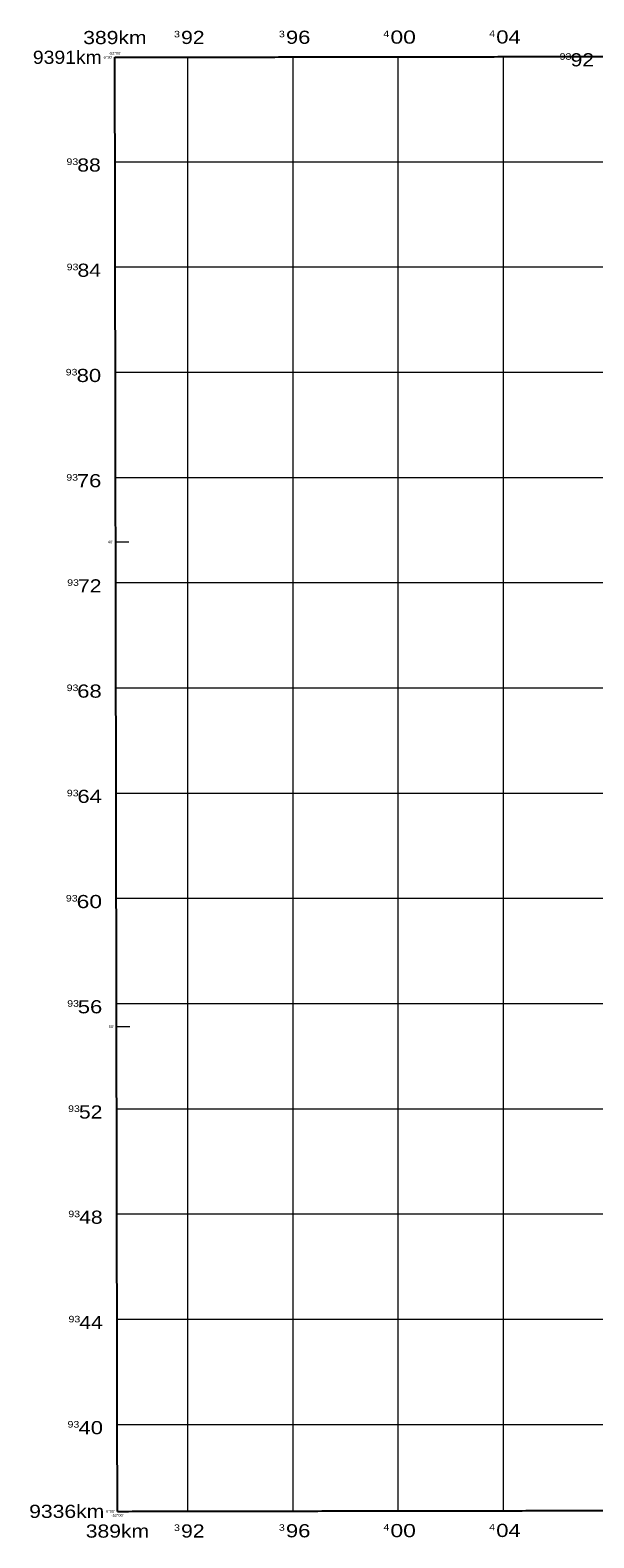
# Model space of a CAD drawing. Extents: x 386 to 448, y 9335.7 to 9393.1.
# Drawn here: x 386 to 407.4, y 9335.7 to 9393 of the extents above; entities that cross this region are included whole.
import ezdxf
from ezdxf.enums import TextEntityAlignment as Align

# ---------------------------------------------------------------- set-up
doc = ezdxf.new("R2010")
doc.units = 0
doc.header["$LTSCALE"] = 0.1
for name, color, linetype, lineweight in [('1', 7, 'Continuous', 25), ('2', 7, 'Continuous', 13), ('4', 7, 'Continuous', 13)]:
    doc.layers.add(name, color=color, linetype=linetype, lineweight=lineweight)
doc.layers.add('5', color=7, linetype='Continuous')
doc.layers.add('6', color=7, linetype='Continuous')

msp = doc.modelspace()

# ---------------------------------------------------------------- linework, layer by layer
at = {"layer": '1'}
for points in [[(389.2279, 9391.9712), (390.3584, 9391.9731), (391.4888, 9391.975), (392.6192, 9391.9768), (393.7496, 9391.9786), (394.8801, 9391.9804), (396.0105, 9391.9822), (397.1409, 9391.984), (398.2713, 9391.9857), (399.4017, 9391.9875), (400.5321, 9391.9892), (401.6626, 9391.9909), (402.793, 9391.9925), (403.9234, 9391.9942), (405.0538, 9391.9958), (406.1841, 9391.9974), (407.3145, 9391.999), (408.4449, 9392.0006), (409.5753, 9392.0021), (410.7057, 9392.0037), (411.8361, 9392.0052), (412.9664, 9392.0067), (414.0968, 9392.0082), (415.2272, 9392.0096), (416.3576, 9392.0111), (417.4879, 9392.0125), (418.6183, 9392.0139), (419.7487, 9392.0153), (420.879, 9392.0166), (422.0094, 9392.018), (423.1397, 9392.0193), (424.2701, 9392.0206), (425.4004, 9392.0219), (426.5308, 9392.0231), (427.6611, 9392.0244), (428.7915, 9392.0256), (429.9218, 9392.0268), (431.0521, 9392.028), (432.1825, 9392.0292), (433.3128, 9392.0303), (434.4431, 9392.0314), (435.5735, 9392.0325), (436.7038, 9392.0336), (437.8341, 9392.0347), (438.9644, 9392.0358), (440.0947, 9392.0368), (441.2251, 9392.0378), (442.3554, 9392.0388), (443.4857, 9392.0398), (444.616, 9392.0407)], [(389.3246, 9336.6921), (389.3225, 9337.8203), (389.3205, 9338.9484), (389.3184, 9340.0766), (389.3164, 9341.2047), (389.3143, 9342.3329), (389.3123, 9343.4611), (389.3103, 9344.5892), (389.3082, 9345.7174), (389.3062, 9346.8455), (389.3042, 9347.9737), (389.3022, 9349.1018), (389.3001, 9350.23), (389.2981, 9351.3581), (389.2961, 9352.4863), (389.2941, 9353.6144), (389.2921, 9354.7426), (389.2901, 9355.8707), (389.2881, 9356.9988), (389.2861, 9358.127), (389.2841, 9359.2551), (389.2821, 9360.3833), (389.2801, 9361.5114), (389.2782, 9362.6396), (389.2762, 9363.7677), (389.2742, 9364.8959), (389.2722, 9366.024), (389.2703, 9367.1522), (389.2683, 9368.2803), (389.2664, 9369.4084), (389.2644, 9370.5366), (389.2624, 9371.6647), (389.2605, 9372.7929), (389.2586, 9373.921), (389.2566, 9375.0492), (389.2547, 9376.1773), (389.2527, 9377.3054), (389.2508, 9378.4336), (389.2489, 9379.5617), (389.247, 9380.6899), (389.245, 9381.818), (389.2431, 9382.9461), (389.2412, 9384.0743), (389.2393, 9385.2024), (389.2374, 9386.3305), (389.2355, 9387.4587), (389.2336, 9388.5868), (389.2317, 9389.715), (389.2298, 9390.8431), (389.2279, 9391.9712)], [(389.3246, 9336.6921), (390.454, 9336.6942), (391.5835, 9336.6962), (392.7129, 9336.6982), (393.8424, 9336.7002), (394.9718, 9336.7022), (396.1012, 9336.7041), (397.2307, 9336.706), (398.3601, 9336.7079), (399.4895, 9336.7098), (400.619, 9336.7117), (401.7484, 9336.7135), (402.8778, 9336.7153), (404.0072, 9336.7171), (405.1366, 9336.7189), (406.266, 9336.7207), (407.3954, 9336.7224), (408.5248, 9336.7241), (409.6542, 9336.7258), (410.7836, 9336.7275), (411.913, 9336.7291), (413.0424, 9336.7308), (414.1718, 9336.7324), (415.3012, 9336.734), (416.4306, 9336.7355), (417.5599, 9336.7371), (418.6893, 9336.7386), (419.8187, 9336.7401), (420.9481, 9336.7416), (422.0774, 9336.7431), (423.2068, 9336.7445), (424.3362, 9336.7459), (425.4655, 9336.7473), (426.5949, 9336.7487), (427.7242, 9336.75), (428.8536, 9336.7514), (429.9829, 9336.7527), (431.1123, 9336.754), (432.2416, 9336.7553), (433.371, 9336.7565), (434.5003, 9336.7577), (435.6297, 9336.7589), (436.759, 9336.7601), (437.8884, 9336.7613), (439.0177, 9336.7624), (440.147, 9336.7636), (441.2764, 9336.7647), (442.4057, 9336.7658), (443.535, 9336.7668), (444.6643, 9336.7679)]]:
    msp.add_spline(points, degree=3, dxfattribs=at)
at = {"layer": '2'}
for points in [[(391.9999, 9336.697), (391.9999, 9340), (391.9999, 9344), (391.9999, 9348), (391.9999, 9352), (391.9999, 9356), (391.9999, 9360), (391.9999, 9364), (391.9999, 9368), (391.9999, 9372), (391.9999, 9376), (391.9999, 9380), (391.9999, 9384), (391.9999, 9388), (391.9999, 9391.9758)], [(395.9999, 9336.7039), (395.9999, 9340), (395.9999, 9344), (395.9999, 9348), (395.9999, 9352), (395.9999, 9356), (395.9999, 9360), (395.9999, 9364), (395.9999, 9368), (395.9999, 9372), (395.9999, 9376), (395.9999, 9380), (395.9999, 9384), (395.9999, 9388), (395.9999, 9391.9822)], [(399.9999, 9336.7107), (399.9999, 9340), (399.9999, 9344), (399.9999, 9348), (399.9999, 9352), (399.9999, 9356), (399.9999, 9360), (399.9999, 9364), (399.9999, 9368), (399.9999, 9372), (399.9999, 9376), (399.9999, 9380), (399.9999, 9384), (399.9999, 9388), (399.9999, 9391.9884)], [(403.9999, 9336.7171), (403.9999, 9340), (403.9999, 9344), (403.9999, 9348), (403.9999, 9352), (403.9999, 9356), (403.9999, 9360), (403.9999, 9364), (403.9999, 9368), (403.9999, 9372), (403.9999, 9376), (403.9999, 9380), (403.9999, 9384), (403.9999, 9388), (403.9999, 9391.9943)], [(389.2346, 9388), (391.9999, 9388), (395.9999, 9388), (399.9999, 9388), (403.9999, 9388), (407.9999, 9388), (411.9999, 9388), (415.9999, 9388), (419.9999, 9388), (423.9999, 9388), (427.9999, 9388), (431.9999, 9388), (435.9999, 9388), (439.9999, 9388), (444, 9388), (444.6194, 9388)], [(389.2413, 9384), (391.9999, 9384), (395.9999, 9384), (399.9999, 9384), (403.9999, 9384), (407.9999, 9384), (411.9999, 9384), (415.9999, 9384), (419.9999, 9384), (423.9999, 9384), (427.9999, 9384), (431.9999, 9384), (435.9999, 9384), (439.9999, 9384), (443.9999, 9384), (444.6228, 9384)], [(389.2481, 9380), (391.9999, 9380), (395.9999, 9380), (399.9999, 9380), (403.9999, 9380), (407.9999, 9380), (411.9999, 9380), (415.9999, 9380), (419.9999, 9380), (423.9999, 9380), (427.9999, 9380), (431.9999, 9380), (435.9999, 9380), (439.9999, 9380), (443.9999, 9380), (444.6262, 9380)], [(389.255, 9376), (391.9999, 9376), (395.9999, 9376), (399.9999, 9376), (403.9999, 9376), (407.9999, 9376), (411.9999, 9376), (415.9999, 9376), (419.9999, 9376), (423.9999, 9376), (427.9999, 9376), (431.9999, 9376), (435.9999, 9376), (439.9999, 9376), (443.9999, 9376), (444.6296, 9376)], [(389.2619, 9372), (391.9999, 9372), (395.9999, 9372), (399.9999, 9372), (403.9999, 9372), (407.9999, 9372), (411.9999, 9372), (415.9999, 9372), (419.9999, 9372), (423.9999, 9372), (427.9999, 9372), (431.9999, 9372), (435.9999, 9372), (439.9999, 9372), (443.9999, 9372), (444.6331, 9372)], [(389.2688, 9368), (391.9999, 9368), (395.9999, 9368), (399.9999, 9368), (403.9999, 9368), (407.9999, 9368), (411.9999, 9368), (415.9999, 9368), (419.9999, 9368), (423.9999, 9368), (427.9999, 9368), (431.9999, 9368), (435.9999, 9368), (439.9999, 9368), (443.9999, 9368), (444.6365, 9368)], [(389.2758, 9364), (391.9999, 9364), (395.9999, 9364), (399.9999, 9364), (403.9999, 9364), (407.9999, 9364), (411.9999, 9364), (415.9999, 9364), (419.9999, 9364), (423.9999, 9364), (427.9999, 9364), (431.9999, 9364), (435.9999, 9364), (439.9999, 9364), (443.9999, 9364), (444.64, 9364)], [(389.2828, 9360), (391.9999, 9360), (395.9999, 9360), (399.9999, 9360), (403.9999, 9360), (407.9999, 9360), (411.9999, 9360), (415.9999, 9360), (419.9999, 9360), (423.9999, 9360), (427.9999, 9360), (431.9999, 9360), (435.9999, 9360), (439.9999, 9360), (444, 9360), (444.6435, 9360)], [(389.2899, 9356), (391.9999, 9356), (395.9999, 9356), (399.9999, 9356), (403.9999, 9356), (407.9999, 9356), (411.9999, 9356), (415.9999, 9356), (419.9999, 9356), (423.9999, 9356), (427.9999, 9356), (431.9999, 9356), (435.9999, 9356), (439.9999, 9356), (443.9999, 9356), (444.6471, 9356)], [(389.297, 9352), (391.9999, 9352), (395.9999, 9352), (399.9999, 9352), (403.9999, 9352), (407.9999, 9352), (411.9999, 9352), (415.9999, 9352), (419.9999, 9352), (423.9999, 9352), (427.9999, 9352), (431.9999, 9352), (435.9999, 9352), (439.9999, 9352), (444, 9352), (444.6506, 9352)], [(389.3041, 9348), (391.9999, 9348), (395.9999, 9348), (399.9999, 9348), (403.9999, 9348), (407.9999, 9348), (411.9999, 9348), (415.9999, 9348), (419.9999, 9348), (423.9999, 9348), (427.9999, 9348), (431.9999, 9348), (435.9999, 9348), (439.9999, 9348), (443.9999, 9348), (444.6542, 9348)], [(389.3113, 9344), (391.9999, 9344), (395.9999, 9344), (399.9999, 9344), (403.9999, 9344), (407.9999, 9344), (411.9999, 9344), (415.9999, 9344), (419.9999, 9344), (423.9999, 9344), (427.9999, 9344), (431.9999, 9344), (435.9999, 9344), (439.9999, 9344), (443.9999, 9344), (444.6578, 9344)], [(389.3186, 9340), (391.9999, 9340), (395.9999, 9340), (399.9999, 9340), (403.9999, 9340), (407.9999, 9340), (411.9999, 9340), (415.9999, 9340), (419.9999, 9340), (423.9999, 9340), (427.9999, 9340), (431.9999, 9340), (435.9999, 9340), (439.9999, 9340), (443.9999, 9340), (444.6614, 9340)]]:
    msp.add_spline(points, degree=3, dxfattribs=at)
at = {"layer": '4'}
for p, q in [((389.2592, 9373.545), (389.7592, 9373.5458)), ((389.2914, 9355.1186), (389.7914, 9355.1194))]:
    msp.add_line(p, q, dxfattribs=at)

# ---------------------------------------------------------------- texts
at = {"layer": '5'}
for s, rotation, width, p in [("-5°30'", 0.088, 1.05, (389.1282, 9391.9211)), ("40'", 0.091, 1.15, (389.1595, 9373.4949)), ("50'", 0.093, 1.15, (389.1917, 9355.0685)), ("-6°00'", 0.096, 1.1, (389.2248, 9336.642))]:
    msp.add_text(s, height=0.1, rotation=rotation, dxfattribs=dict(at, width=width)).set_placement(p, align=Align.RIGHT)
at = {"layer": '5', "width": 1.1}
for rotation, p in [(0.097, (389.2279, 9392.0713)), (0.103, (389.3251, 9336.4922))]:
    msp.add_text("-52°00'", height=0.1, rotation=rotation, dxfattribs=at).set_placement(p, align=Align.CENTER)
at = {"layer": '6', "width": 1.2}
for p in [(389.228, 9392.4713), (389.3246, 9335.6922)]:
    msp.add_text('389km', height=0.5, dxfattribs=at).set_placement(p, align=Align.CENTER)
at = {"layer": '6'}
for s, height, width, p in [('3', 0.25, 1.2, (391.4773, 9392.7259)), ('92', 0.5, 1.2, (391.7441, 9392.4759)), ('3', 0.25, 1.2, (395.4635, 9392.7323)), ('96', 0.5, 1.25, (395.7303, 9392.4823)), ('4', 0.25, 1.2, (399.436, 9392.7384)), ('00', 0.5, 1.3, (399.7027, 9392.4885)), ('4', 0.25, 1.2, (403.4576, 9392.7443)), ('04', 0.5, 1.25, (403.7244, 9392.4944)), ('3', 0.25, 1.2, (391.4773, 9335.947)), ('92', 0.5, 1.2, (391.7441, 9335.6971)), ('3', 0.25, 1.2, (395.4635, 9335.954)), ('96', 0.5, 1.25, (395.7303, 9335.704)), ('4', 0.25, 1.2, (399.436, 9335.9607)), ('00', 0.5, 1.3, (399.7027, 9335.7108)), ('4', 0.25, 1.2, (403.4576, 9335.9672)), ('04', 0.5, 1.25, (403.7244, 9335.7172))]:
    msp.add_text(s, height=height, dxfattribs=dict(at, width=width)).set_placement(p)
for s, height, width, p in [('9391km', 0.5, 1.1, (388.728, 9391.7213)), ('93', 0.25, 1.2, (406.5809, 9391.8751)), ('92', 0.5, 1.2, (407.442, 9391.625)), ('93', 0.25, 1.2, (387.835, 9387.8751)), ('88', 0.5, 1.2, (388.6922, 9387.625)), ('93', 0.25, 1.2, (387.8417, 9383.8751)), ('84', 0.5, 1.2, (388.699, 9383.625)), ('93', 0.25, 1.2, (387.8052, 9379.8751)), ('80', 0.5, 1.25, (388.7058, 9379.625)), ('93', 0.25, 1.2, (387.8279, 9375.8751)), ('76', 0.5, 1.25, (388.7126, 9375.625)), ('93', 0.25, 1.2, (387.8623, 9371.8751)), ('72', 0.5, 1.2, (388.7195, 9371.625)), ('93', 0.25, 1.2, (387.8417, 9367.8751)), ('68', 0.5, 1.25, (388.7265, 9367.625)), ('93', 0.25, 1.2, (387.8487, 9363.8751)), ('64', 0.5, 1.25, (388.7334, 9363.625)), ('93', 0.25, 1.2, (387.8124, 9359.8751)), ('60', 0.5, 1.3, (388.7405, 9359.625)), ('93', 0.25, 1.2, (387.8628, 9355.8751)), ('56', 0.5, 1.25, (388.7475, 9355.625)), ('93', 0.25, 1.2, (387.8974, 9351.8751)), ('52', 0.5, 1.2, (388.7546, 9351.625)), ('93', 0.25, 1.2, (387.9045, 9347.8751)), ('48', 0.5, 1.2, (388.7618, 9347.625)), ('93', 0.25, 1.2, (387.9117, 9343.8751)), ('44', 0.5, 1.2, (388.769, 9343.625)), ('93', 0.25, 1.2, (387.8757, 9339.8751)), ('40', 0.5, 1.25, (388.7762, 9339.625)), ('9336km', 0.5, 1.2, (388.8246, 9336.4422))]:
    msp.add_text(s, height=height, dxfattribs=dict(at, width=width)).set_placement(p, align=Align.RIGHT)

doc.saveas('drawing.dxf')
